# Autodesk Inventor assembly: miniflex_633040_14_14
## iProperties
Shininess: 64.0
Length Units: 11269
Angle Units: 11279
Time Units: 11290
Mass Units: 11283
Length Display Precision: 3
Angle Display Precision: 2
Compacted: True
Created: 2005-02
Part Number: miniflex_633040_14_14
Document SubType Name: Assembly
Designer: LEGERET Philippe
Catalog Web Link: www.traceparts.com
Description: Accouplement élastique Miniflex 633040 14 14
Vendor: PAULSTRA
Density: 0.0
Volumn: 0.0
Area: 0.0
PropertySet Name: Model Information
Control State: 0
Master: False
Checked Out: False
REFERENCE: 633040
Author: Trace Parts S.A.
